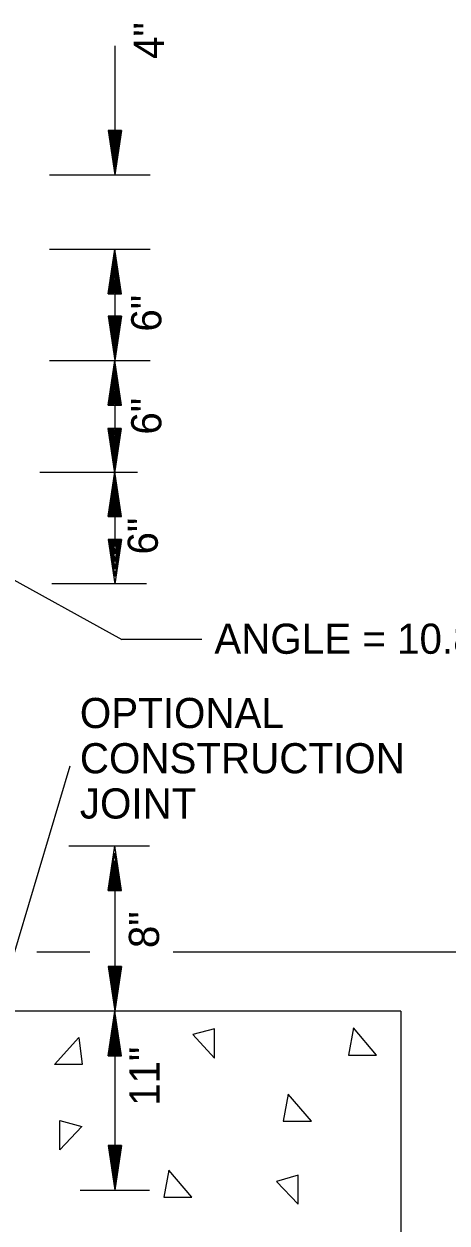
# Model space of a CAD drawing. Extents: x 714919 to 718439, y 1619644 to 1621844.
# Drawn here: x 717916.1 to 718061.5, y 1620506.3 to 1620918.6 of the extents above; entities that cross this region are included whole.
import ezdxf

# ---------------------------------------------------------------- set-up
doc = ezdxf.new("R2010")
doc.units = 0
for name, color, linetype in [('R_Annotation', 7, 'Continuous'), ('R_Dimension', 7, 'Continuous'), ('T_Drafting', 7, 'Continuous')]:
    doc.layers.add(name, color=color, linetype=linetype)

msp = doc.modelspace()

# ---------------------------------------------------------------- linework, layer by layer
at = {"layer": 'R_Annotation'}
for p, q in [((717873.06, 1620749.11), (717949.7, 1620706.95)), ((717977.17, 1620706.95), (717949.7, 1620706.95)), ((717931.87, 1620663.32), (717906.65, 1620579.03))]:
    msp.add_line(p, q, dxfattribs=at)
at = {"layer": 'R_Dimension'}
for p, q in [((717947.29, 1620911.04), (717947.29, 1620866.71)), ((717944.96, 1620882.01), (717947.29, 1620866.71)), ((717949.54, 1620882.01), (717944.96, 1620882.01)), ((717945.39, 1620882.01), (717947.29, 1620869.22)), ((717945.74, 1620882.01), (717947.29, 1620871.9)), ((717946.08, 1620882.01), (717947.29, 1620874.49)), ((717946.51, 1620882.01), (717947.29, 1620877.08)), ((717946.86, 1620882.01), (717947.29, 1620879.59)), ((717949.54, 1620882.01), (717947.29, 1620866.71)), ((717948.07, 1620882.01), (717947.29, 1620877.08)), ((717948.76, 1620882.01), (717947.29, 1620871.9)), ((717949.19, 1620882.01), (717947.29, 1620869.22)), ((717948.41, 1620882.01), (717947.29, 1620874.49)), ((717947.64, 1620882.01), (717947.29, 1620879.59)), ((717924.83, 1620866.71), (717959.39, 1620866.71)), ((717924.83, 1620841.14), (717959.39, 1620841.14)), ((717944.96, 1620825.85), (717947.29, 1620841.14)), ((717947.29, 1620841.14), (717947.29, 1620740.14)), ((717949.54, 1620825.85), (717947.29, 1620841.14)), ((717945.39, 1620825.85), (717947.29, 1620838.63)), ((717945.74, 1620825.85), (717947.29, 1620835.95)), ((717949.19, 1620825.85), (717947.29, 1620838.63)), ((717948.76, 1620825.85), (717947.29, 1620835.95)), ((717946.08, 1620825.85), (717947.29, 1620833.45)), ((717948.41, 1620825.85), (717947.29, 1620833.45)), ((717946.51, 1620825.85), (717947.29, 1620830.77)), ((717946.86, 1620825.85), (717947.29, 1620828.27)), ((717948.07, 1620825.85), (717947.29, 1620830.77)), ((717947.64, 1620825.85), (717947.29, 1620828.27)), ((717944.96, 1620825.85), (717949.54, 1620825.85)), ((717944.96, 1620818.16), (717947.29, 1620802.86)), ((717949.54, 1620818.16), (717944.96, 1620818.16)), ((717945.39, 1620818.16), (717947.29, 1620805.37)), ((717945.74, 1620818.16), (717947.29, 1620808.05)), ((717946.08, 1620818.16), (717947.29, 1620810.55)), ((717946.51, 1620818.16), (717947.29, 1620813.15)), ((717946.86, 1620818.16), (717947.29, 1620815.74)), ((717949.54, 1620818.16), (717947.29, 1620802.86)), ((717948.07, 1620818.16), (717947.29, 1620813.15)), ((717948.76, 1620818.16), (717947.29, 1620808.05)), ((717949.19, 1620818.16), (717947.29, 1620805.37)), ((717948.41, 1620818.16), (717947.29, 1620810.55)), ((717947.64, 1620818.16), (717947.29, 1620815.74)), ((717924.83, 1620802.86), (717959.39, 1620802.86)), ((717944.96, 1620787.48), (717947.29, 1620802.86)), ((717949.54, 1620787.48), (717947.29, 1620802.86)), ((717945.39, 1620787.48), (717947.29, 1620800.27)), ((717949.19, 1620787.48), (717947.29, 1620800.27)), ((717945.74, 1620787.48), (717947.29, 1620797.59)), ((717946.08, 1620787.48), (717947.29, 1620795.09)), ((717948.76, 1620787.48), (717947.29, 1620797.59)), ((717948.41, 1620787.48), (717947.29, 1620795.09)), ((717946.51, 1620787.48), (717947.29, 1620792.5)), ((717948.07, 1620787.48), (717947.29, 1620792.5)), ((717944.96, 1620787.48), (717949.54, 1620787.48)), ((717946.86, 1620787.48), (717947.29, 1620789.99)), ((717947.64, 1620787.48), (717947.29, 1620789.99)), ((717944.87, 1620779.45), (717947.2, 1620764.07)), ((717949.45, 1620779.45), (717944.87, 1620779.45)), ((717945.22, 1620779.45), (717947.2, 1620766.66)), ((717945.65, 1620779.45), (717947.2, 1620769.34)), ((717945.99, 1620779.45), (717947.2, 1620771.85)), ((717946.43, 1620779.45), (717947.2, 1620774.44)), ((717946.77, 1620779.45), (717947.2, 1620777.03)), ((717949.45, 1620779.45), (717947.2, 1620764.07)), ((717947.9, 1620779.45), (717947.2, 1620774.44)), ((717948.67, 1620779.45), (717947.2, 1620769.34)), ((717949.11, 1620779.45), (717947.2, 1620766.66)), ((717948.33, 1620779.45), (717947.2, 1620771.85)), ((717947.55, 1620779.45), (717947.2, 1620777.03)), ((717921.54, 1620764.5), (717930.01, 1620764.5)), ((717924.91, 1620764.5), (717943.66, 1620764.5)), ((717941.33, 1620764.5), (717955.07, 1620764.5)), ((717941.33, 1620764.5), (717947.46, 1620764.5)), ((717944.96, 1620764.24), (717944.96, 1620764.5)), ((717944.96, 1620764.24), (717944.96, 1620764.5)), ((717944.96, 1620764.24), (717944.96, 1620764.5)), ((717945.04, 1620749.21), (717947.29, 1620764.59)), ((717945.39, 1620749.21), (717947.29, 1620762.08)), ((717949.62, 1620749.21), (717947.29, 1620764.59)), ((717949.28, 1620749.21), (717947.29, 1620762.08)), ((717945.82, 1620749.21), (717947.29, 1620759.4)), ((717948.85, 1620749.21), (717947.29, 1620759.4)), ((717946.17, 1620749.21), (717947.29, 1620756.81)), ((717946.6, 1620749.21), (717947.29, 1620754.22)), ((717948.5, 1620749.21), (717947.29, 1620756.81)), ((717948.07, 1620749.21), (717947.29, 1620754.22)), ((717945.04, 1620749.21), (717949.62, 1620749.21)), ((717946.95, 1620749.21), (717947.29, 1620751.71)), ((717947.72, 1620749.21), (717947.29, 1620751.71)), ((717945.04, 1620741.35), (717947.29, 1620726.05)), ((717949.62, 1620741.35), (717945.04, 1620741.35)), ((717945.39, 1620741.35), (717947.29, 1620728.56)), ((717945.82, 1620741.35), (717947.29, 1620731.24)), ((717946.17, 1620741.35), (717947.29, 1620733.74)), ((717946.6, 1620741.35), (717947.29, 1620736.34)), ((717946.95, 1620741.35), (717947.29, 1620738.93)), ((717949.62, 1620741.35), (717947.29, 1620726.05)), ((717948.07, 1620741.35), (717947.29, 1620736.34)), ((717948.85, 1620741.35), (717947.29, 1620731.24)), ((717949.28, 1620741.35), (717947.29, 1620728.56)), ((717948.5, 1620741.35), (717947.29, 1620733.74)), ((717947.72, 1620741.35), (717947.29, 1620738.93)), ((717925.69, 1620726.14), (717936.75, 1620726.14)), ((717932.17, 1620726.14), (717936.75, 1620726.14)), ((717934.42, 1620726.14), (717936.15, 1620726.14)), ((717934.42, 1620726.14), (717958.18, 1620726.14)), ((717934.42, 1620726.14), (717940.55, 1620726.14)), ((717934.42, 1620726.14), (717940.55, 1620726.14)), ((717931.49, 1620635.98), (717959.17, 1620635.98)), ((717945.04, 1620620.6), (717947.29, 1620635.98)), ((717949.62, 1620620.6), (717947.29, 1620635.98)), ((717945.39, 1620620.6), (717947.29, 1620633.48)), ((717945.82, 1620620.6), (717947.29, 1620630.8)), ((717949.28, 1620620.6), (717947.29, 1620633.48)), ((717948.85, 1620620.6), (717947.29, 1620630.8)), ((717947.29, 1620630.55), (717947.29, 1620579.17)), ((717946.17, 1620620.6), (717947.29, 1620628.21)), ((717946.6, 1620620.6), (717947.29, 1620625.61)), ((717948.5, 1620620.6), (717947.29, 1620628.21)), ((717948.07, 1620620.6), (717947.29, 1620625.61)), ((717946.95, 1620620.6), (717947.29, 1620623.11)), ((717947.72, 1620620.6), (717947.29, 1620623.11)), ((717945.04, 1620620.6), (717949.62, 1620620.6)), ((717938.69, 1620599.42), (717920.52, 1620599.42)), ((718104.37, 1620599.42), (717967.39, 1620599.42)), ((717945.04, 1620594.47), (717947.29, 1620579.17)), ((717949.62, 1620594.47), (717945.04, 1620594.47)), ((717945.39, 1620594.47), (717947.29, 1620581.68)), ((717945.82, 1620594.47), (717947.29, 1620584.36)), ((717946.17, 1620594.47), (717947.29, 1620586.86)), ((717946.6, 1620594.47), (717947.29, 1620589.46)), ((717946.95, 1620594.47), (717947.29, 1620592.05)), ((717949.62, 1620594.47), (717947.29, 1620579.17)), ((717948.07, 1620594.47), (717947.29, 1620589.46)), ((717948.85, 1620594.47), (717947.29, 1620584.36)), ((717949.28, 1620594.47), (717947.29, 1620581.68)), ((717948.5, 1620594.47), (717947.29, 1620586.86)), ((717947.72, 1620594.47), (717947.29, 1620592.05)), ((717945.04, 1620563.8), (717947.29, 1620579.17)), ((717945.39, 1620563.8), (717947.29, 1620576.67)), ((717947.29, 1620579.17), (717947.29, 1620517.6)), ((717949.62, 1620563.8), (717947.29, 1620579.17)), ((717949.28, 1620563.8), (717947.29, 1620576.67)), ((717945.82, 1620563.8), (717947.29, 1620573.99)), ((717948.85, 1620563.8), (717947.29, 1620573.99)), ((717946.17, 1620563.8), (717947.29, 1620571.4)), ((717946.6, 1620563.8), (717947.29, 1620568.81)), ((717948.5, 1620563.8), (717947.29, 1620571.4)), ((717948.07, 1620563.8), (717947.29, 1620568.81)), ((717945.04, 1620563.8), (717949.62, 1620563.8)), ((717946.95, 1620563.8), (717947.29, 1620566.3)), ((717947.72, 1620563.8), (717947.29, 1620566.3)), ((717945.04, 1620532.89), (717947.29, 1620517.6)), ((717949.62, 1620532.89), (717945.04, 1620532.89)), ((717945.39, 1620532.89), (717947.29, 1620520.1)), ((717945.82, 1620532.89), (717947.29, 1620522.78)), ((717946.17, 1620532.89), (717947.29, 1620525.29)), ((717946.6, 1620532.89), (717947.29, 1620527.88)), ((717946.95, 1620532.89), (717947.29, 1620530.47)), ((717949.62, 1620532.89), (717947.29, 1620517.6)), ((717948.07, 1620532.89), (717947.29, 1620527.88)), ((717948.85, 1620532.89), (717947.29, 1620522.78)), ((717949.28, 1620532.89), (717947.29, 1620520.1)), ((717948.5, 1620532.89), (717947.29, 1620525.29)), ((717947.72, 1620532.89), (717947.29, 1620530.47)), ((717935.41, 1620517.6), (717959.17, 1620517.6))]:
    msp.add_line(p, q, dxfattribs=at)
at = {"layer": 'T_Drafting'}
for p, q in [((718045.57, 1620579.17), (717912.47, 1620579.17)), ((718045.57, 1620579.17), (718045.57, 1620459.19)), ((717981.53, 1620573.04), (717974.1, 1620571.14)), ((717981.53, 1620563.02), (717981.53, 1620573.04)), ((718029.28, 1620573.36), (718027.55, 1620564.03)), ((718037.23, 1620564.03), (718029.28, 1620573.36)), ((717926.61, 1620560.77), (717934.91, 1620570.1)), ((717934.91, 1620570.1), (717936.11, 1620560.77)), ((717974.1, 1620571.14), (717981.53, 1620563.02)), ((718027.55, 1620564.03), (718037.23, 1620564.03)), ((717936.11, 1620560.77), (717926.61, 1620560.77)), ((718006.91, 1620550.59), (718005.18, 1620541.26)), ((718014.86, 1620541.26), (718006.91, 1620550.59)), ((717928.39, 1620531.49), (717928.39, 1620541.51)), ((717928.39, 1620541.51), (717936, 1620539.43)), ((717936, 1620539.43), (717928.39, 1620531.49)), ((718005.18, 1620541.26), (718014.86, 1620541.26)), ((717965.87, 1620524.5), (717964.14, 1620515.18)), ((717973.81, 1620515.18), (717965.87, 1620524.5)), ((718010.29, 1620522.77), (718002.87, 1620520.52)), ((718010.29, 1620512.75), (718010.29, 1620522.77)), ((718002.87, 1620520.52), (718010.29, 1620512.75)), ((717964.14, 1620515.18), (717973.81, 1620515.18))]:
    msp.add_line(p, q, dxfattribs=at)

# ---------------------------------------------------------------- texts
at = {"layer": 'R_Annotation'}
for s, height, p in [('ANGLE = 10.8', 10.3685, (717981.49, 1620702.02)), ('OPTIONAL', 10.369, (717935.27, 1620676.47)), ('CONSTRUCTION', 10.3685, (717935.27, 1620660.92)), ('JOINT', 10.369, (717935.27, 1620645.37))]:
    msp.add_text(s, height=height, dxfattribs=at).set_placement(p)
at = {"layer": 'R_Dimension'}
for s, p in [('4"', (717964.14, 1620906.54)), ('6"', (717963.27, 1620812.8)), ('6"', (717963.27, 1620777.38)), ('6"', (717962.07, 1620736.16)), ('8"', (717962.48, 1620600.81)), ('11"', (717962.68, 1620546.55))]:
    msp.add_text(s, height=10.369, rotation=90, dxfattribs=at).set_placement(p)

doc.saveas('drawing.dxf')
